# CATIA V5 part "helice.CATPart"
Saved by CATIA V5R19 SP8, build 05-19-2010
Part number: helice
Bounding box of the stored display mesh (mm): x -17.321 to 17.321, y -30 to 195, z -10 to 20
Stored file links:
  G:\EU_thinkMotion\CFAO_2010\MMS_groupe2\MMS_groupe2\A reprendre\splanchenault\Planchenault\helice.CATPart
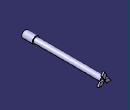
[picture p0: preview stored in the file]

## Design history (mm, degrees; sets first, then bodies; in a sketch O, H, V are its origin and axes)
Body1 (main body)
  Sketch1 on xy-plane, origin (0, 0, 0), H (1, 0, 0), V (0, 1, 0)
    line L1 (0, 0) -> (0, -30)
    line L2 (0, -30) -> (-10, -30)
    line L3 (-10, -30) -> (-10, 0)
    point P3 (-10, 0)
    line L4 (-10, 0) -> (-7.5, 0)
    line L5 (-7.5, 0) -> (-7.5, 190)
    line L6 (-7.5, 190) -> (0, 190)
    point P6 (0, 190)
    length L6 = 7.5
    vertical: L1 V, L3 V, L5 V
    horizontal: L2 H, L4 H, L6 H
    coincidence: P3 H, P6 V
  Shaft1: profile Sketch1, axis Sketch1.L1, angle 360
  Sketch2 on face of Shaft1 from Sketch1.L6, origin (0, 190, 0), H (-1, 0, 0), V (0, 0, 1)
    construction line L1 (19.3649, -11.1803) -> (-19.3649, 11.1803)
    axis line L2 (-19.3649, -11.1803) -> (19.3649, 11.1803)
    line L3 (0, 0) -> (5.7735, 10)
    point P5 (5.7735, 10)
    line L4 (5.7735, 10) -> (0, 20)
    point P6 (0, 20)
    line L5 (0, 20) -> (-5.7735, 10)
    point P7 (-5.7735, 10)
    line L6 (-5.7735, 10) -> (0, 0)
    point P8 (-11.547, 0)
    point P9 (-17.3205, -10)
    line L7 (-17.3205, -10) -> (-11.547, 0)
    point P10 (-5.7735, -10)
    line L8 (-5.7735, -10) -> (-17.3205, -10)
    point P11 (0, 0)
    line L9 (0, 0) -> (-5.7735, -10)
    line L10 (-11.547, 0) -> (0, 0)
    point P12 (0, 0)
    point P13 (5.7735, -10)
    line L11 (5.7735, -10) -> (0, 0)
    point P14 (17.3205, -10)
    line L12 (17.3205, -10) -> (5.7735, -10)
    point P15 (11.547, 0)
    line L13 (11.547, 0) -> (17.3205, -10)
    line L14 (0, 0) -> (11.547, 0)
    angle L1 V = 60
    angle V L2 = 60
    coincidence: L2 O, P6 V, O P11, O P12, P11 P12
    perpendicularity: L3 L1, L4 L2
    parallelism: L5 L3, L6 L4
    symmetry: P7 P8 L1, P6 P9 L1, L5 L7 L1, P5 P10 L1, L4 L8 L1, O P11 L1, L3 L9 L1, L6 L10 L1, O P12 L2, P7 P13 L2, L6 L11 L2, P6 P14 L2, L5 L12 L2, P5 P15 L2, L4 L13 L2, L3 L14 L2
  Pad1: profile Sketch2, direction (0, 1, 0), length 5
